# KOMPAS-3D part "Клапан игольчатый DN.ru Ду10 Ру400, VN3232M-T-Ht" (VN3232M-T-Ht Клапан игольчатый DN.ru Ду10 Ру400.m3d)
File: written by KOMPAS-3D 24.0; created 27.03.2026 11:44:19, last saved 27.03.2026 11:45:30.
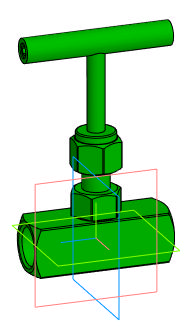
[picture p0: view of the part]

Document properties: Автор: Илья; Полное имя файла: D:\Обмен\Заказы с фриланса\DN.ru\VNxxM-T-Ht Клапан игольчатый DN.ru Ду8-50 Ру400\VN3232M-T-Ht Клапан игольчатый DN.ru Ду8-50 Ру400\DN10\VN3232M-T-Ht Клапан игольчатый DN.ru Ду10 Ру400.m3d

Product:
- Body: Body3  | qty 1
    Масса: 0.224966
- Part/product: Клапан игольчатый DN.ru Ду10 Ру400  | designation VN3232M-T-Ht
    Масса: 0.4
    Раздел спецификации: Прочие изделия
    Примечание: D090-02130

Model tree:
1. Body3  (labels: Body3)

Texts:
  VN3232M-T-Ht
